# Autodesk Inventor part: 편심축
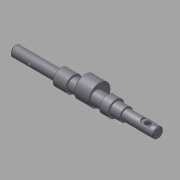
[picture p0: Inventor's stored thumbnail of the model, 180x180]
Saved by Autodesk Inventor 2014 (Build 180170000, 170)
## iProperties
Company: 한국ATC센터
Created: 2015-12
Part Number: 편심축
Document SubType Name: Modeling
Designer: mdu
Density: 7.86 g/cm^3
Mass: 248.518 g
Surface Area: 94.9962 cm^2
Volume: 31.6181 cm^3
Material: 강철, 연강
Appearance: 강철
Author: mdu
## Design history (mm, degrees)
sketch "스케치1"
  geometry: L1 (-84.5, 0)-(84.5, 0); L2 (-84.5, 0)-(-84.5, 6); L3 (-84.5, 6)-(-30.5, 6); L4 (-30.5, 6)-(-30.5, 9.5); L5 (-30.5, 9.5)-(-15.5, 9.5); L6 (-15.5, 9.5)-(-15.5, 7.5); L7 (-15.5, 7.5)-(46.5, 7.5); L8 (84.5, 6)-(84.5, 0); L9 (34.5, 7.5)-(34.5, 9.5); L10 (34.5, 9.5)-(24.5, 9.5); L11 (24.5, 9.5)-(24.5, 7.5); L12 (46.5, 7.5)-(46.5, 6); L13 (46.5, 6)-(84.5, 6); 2 further points
  constraints: 26 end point, 6 parallel, 6 perpendicular, 2 point on line, 1 coincident, 1 horizontal, 1 midpoint
  dimensions: "d1" = 12 diameter of L3 L1; "d2" = 15 diameter of L7 L1; "d4" = 15 distance of L4.end L5.end; "d5" = 19 diameter of L5 L1; "d24" = 10 distance of L9.end L10.end; "d25" = 19 diameter of L10 L1; "d27" = 40 distance between parallel lines of L11 L6; "d28" = 54 distance of L2.end L3.end; "d29" = 50 distance between parallel lines of L8 L9; "d41" = 38 distance between parallel lines of L8 L12; "d42" = 12 diameter of L13 L1
revolve "회전1" stored, may be unused: angle "d6" = 90 deg
node "작업 평면1"
sketch "스케치2"
  geometry: C1 r 7.5 at (0, 0) reference; C2 r 12.5 at (0, 4.5); 1 further point
  constraints: 1 centre point, 1 vertical alignment
  dimensions: "d8" = 4.5 distance of point (0, 0) C2.centre; "d9" = 25 diameter of C2
extrude "돌출1" join sketch "스케치2" distance "d10" = 18; taper "d11" = 0 deg
chamfer "모따기1" distance "d12" = 1; stored, may be unused: second distance "d13" = 2, angle "d14" = 45 deg
chamfer "모따기2" distance "d15" = 0.5; stored, may be unused: second distance "d16" = 2, angle "d17" = 45 deg
node "작업 평면2"
sketch "스케치3"
  geometry: L1 (4, -2)-(18, -2); L2 (18, 2)-(4, 2); L3 (27, 5)-(27, -5) reference; A1 r 2 centre (18, 0) between (18, -2) and (18, 2); A2 r 2 centre (4, 0) between (4, 2) and (4, -2); 2 further points
  constraints: 4 end point, 4 point on circle, 4 tangent, 2 centre point, 1 horizontal, 1 horizontal alignment, 1 midpoint, 1 parallel
  dimensions: "d18" = 7 distance edge to line of A1 L3; "d19" = 4 distance between parallel lines of L2 L1; "d20" = 18 dimension on A1 A2
extrude "돌출2" cut sketch "스케치3" distance "d21" = 2.5; taper "d22" = 0 deg
revolve "회전2" stored, may be unused: angle "d26" = 90 deg
node "작업 평면3"
sketch "스케치4"
  geometry: L1 (44, 5)-(44, -5) reference; 2 further points
  constraints: 1 horizontal alignment
  dimensions: "d30" = 12 distance from line of point (32, 0) L1
hole "구멍1" sketch "스케치4" at (32, 0) diameter "d31" = 6; stored, may be unused: countersink angle "d35" = 90 deg, drill point angle "d37" = 118 deg; dims "d32" = 6, "d33" = 14, "d34" = 3, "d36" = 8
node "작업 평면4"
sketch "스케치5"
  geometry: C1 r 3 at (32, 0) reference; C2 r 8 at (32, 0); 2 further points
  constraints: 1 centre point, 1 coincident, 1 other
  dimensions: "d38" = 16 diameter of C2
extrude "돌출3" cut sketch "스케치5" distance "d39" = 3; taper "d40" = 0 deg
sketch "스케치6"
  geometry: L1 (-83.5, -6)-(-30.5, -6) reference; L2 (-84.5, -5)-(-84.5, 5) reference; L3 (-83.5, 6)-(-30.5, 6) reference; L4 (-62.5, 6)-(-62.5, -6); L5 (-62.5, -6)-(-61, -6); L6 (-62.5, -4.5)-(-61, -6); L7 (-62.5, -6)-(-62.5, -4.5); 2 further points
  constraints: 8 end point, 4 point on line, 2 perpendicular, 1 coincident
  dimensions: "d43" = 22 distance between parallel lines of L4 L2; "d44" = 45 deg angle of L6 L7; "d45" = 3 diameter of L5.end L4
revolve "회전3" stored, may be unused: angle "d46" = 90 deg
node "작업점1"
chamfer "모따기3" distance "d47" = 0.5; stored, may be unused: second distance "d48" = 2, angle "d49" = 45 deg
node "솔리드1"
node "투영된 루프1"
other parameters: "d7" = 8.5
